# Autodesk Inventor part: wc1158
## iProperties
Shininess: 64.0
Length Units: 11272
Angle Units: 11279
Time Units: 11290
Mass Units: 11286
Length Display Precision: 3
Angle Display Precision: 2
Compacted: True
Part Number: wc1158
Document SubType Name: Modeling
Created: 2004-08
Designer: John Blackburn
Manufacturer: Standard
Standards Organization: Custom
Density: 0.0
Volumn: 0.0
Area: 0.0
PropertySet Name: Model Information
Control State: 0
Master: False
Checked Out: False
Author: John Blackburn
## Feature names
1. Base1
